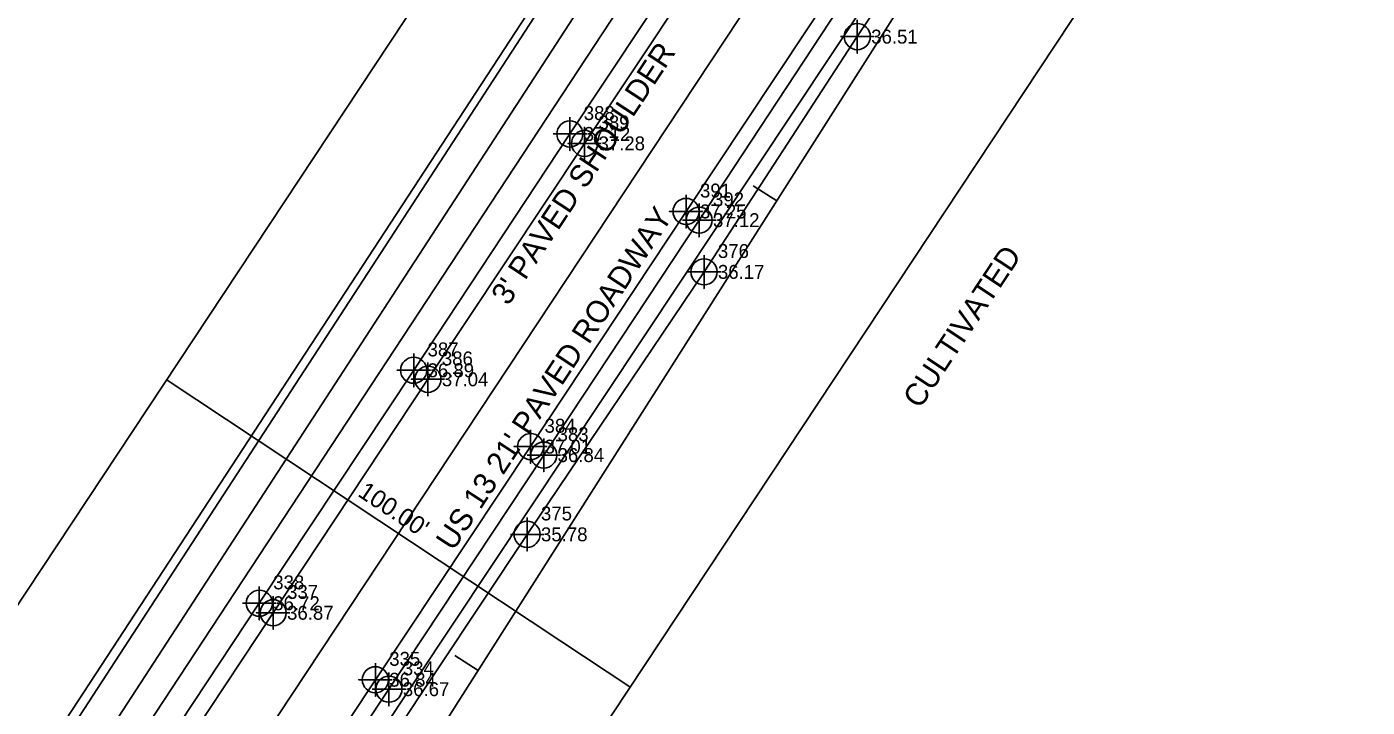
# Model space of a CAD drawing. Extents: x 2603627 to 2605187, y 896619 to 899063.
# Drawn here: x 2604841.7 to 2605082.8, y 898680.4 to 898802.7 of the extents above; entities that cross this region are included whole.
import ezdxf

# ---------------------------------------------------------------- set-up
doc = ezdxf.new("R2010")
doc.units = 0
for name, color, linetype in [('Exist Horizontal Alignment', 7, 'Continuous'), ('Exist Horizontal Baseline Alignment', 7, 'Continuous'), ('Exist Horizontal Baseline Alignment Tick small', 7, 'Continuous'), ('Exist Other Culture Area Outline Text', 7, 'Continuous'), ('Exist Right of Way Line', 7, 'Continuous'), ('Exist Right of Way Width CELL', 7, 'Continuous'), ('Exist Roads EOP', 7, 'Continuous'), ('Exist Roads EOP Cogo Elevation', 7, 'Continuous'), ('Exist Roads EOP Cogo Number', 7, 'Continuous'), ('Exist Roads EOP Cogo Point CELL', 7, 'Continuous'), ('Exist Roads EOP Text', 7, 'Continuous'), ('Exist Roads EOT', 7, 'Continuous'), ('Exist Roads EOT Cogo Elevation', 7, 'Continuous'), ('Exist Roads EOT Cogo Number', 7, 'Continuous'), ('Exist Roads EOT Cogo Point CELL', 7, 'Continuous'), ('Exist Roads EOT Text', 7, 'Continuous'), ('Exist Utilities Telephone UG Cable SUE LOS C', 7, 'Continuous'), ('Exist Utilities Telephone UG FO SUE LOS C', 7, 'Continuous'), ('Exist Utilities Water UG Line SUE LOS B', 7, 'Continuous'), ('Exist Utilities Water UG Line SUE LOS B Cogo Elevation', 7, 'Continuous'), ('Exist Utilities Water UG Line SUE LOS B Cogo Number', 7, 'Continuous'), ('Exist Utilities Water UG Line SUE LOS B Cogo Point CELL', 7, 'Continuous')]:
    doc.layers.add(name, color=color, linetype=linetype)

# ---------------------------------------------------------------- blocks, each defined once
blk = doc.blocks.new('EXIST ROADS EOP COGO POINT')
at = {"layer": 'Exist Roads EOP Cogo Point CELL'}
blk.add_lwpolyline([(0, 0.06), (0, -0.06), (0, 0), (0.06, 0), (-0.06, 0)], dxfattribs=at)
blk.add_circle((0, 0), 0.0469, dxfattribs=at)
blk = doc.blocks.new('EXIST ROADS EOT COGO POINT')
at = {"layer": 'Exist Roads EOT Cogo Point CELL'}
blk.add_lwpolyline([(0, 0.06), (0, -0.06), (0, 0), (-0.06, 0), (0.06, 0)], dxfattribs=at)
blk.add_circle((0, 0), 0.0469, dxfattribs=at)
blk = doc.blocks.new('EXIST UTILITIES WATER UG LINE SUE LOS B COGO POINT')
at = {"layer": 'Exist Utilities Water UG Line SUE LOS B Cogo Point CELL'}
blk.add_lwpolyline([(0, 0.06), (0, -0.06), (0, 0), (0.06, 0), (-0.06, 0)], dxfattribs=at)
blk.add_circle((0, 0), 0.0469, dxfattribs=at)

msp = doc.modelspace()

# ---------------------------------------------------------------- linework, layer by layer
at = {"layer": 'Exist Horizontal Alignment'}
msp.add_line((2604681.44, 898368.79), (2605041.11, 898911.74), dxfattribs=at)
at = {"layer": 'Exist Horizontal Baseline Alignment'}
msp.add_line((2604793.6, 898483.9), (2605028.26, 898852.56), dxfattribs=at)
at = {"layer": 'Exist Horizontal Baseline Alignment Tick small'}
for p, q in [((2604976.59, 898771.39), (2604972.37, 898774.07)), ((2604922.89, 898687.03), (2604918.68, 898689.71))]:
    msp.add_line(p, q, dxfattribs=at)
at = {"layer": 'Exist Right of Way Line'}
for p, q in [((2604639.76, 898396.41), (2604999.42, 898939.36)), ((2604723.13, 898341.18), (2605082.79, 898884.13))]:
    msp.add_line(p, q, dxfattribs=at)
at = {"layer": 'Exist Right of Way Width CELL'}
for p in [(2604866.8, 898739.31), (2604950.17, 898684.08)]:
    msp.add_line(p, (2604937.78, 898692.29), dxfattribs=at)
at = {"layer": 'Exist Roads EOP'}
for points in [[(2604577.96, 898237.27), (2604606.45, 898281.24), (2604633.89, 898322.5), (2604662.45, 898365.47), (2604690.62, 898408.06), (2604717.29, 898448.09), (2604745.46, 898490.11), (2604773.6, 898532.6), (2604800.88, 898573.95), (2604828.34, 898615.46), (2604855.1, 898656.15), (2604883.53, 898699.09), (2604911.29, 898740.95), (2604939.38, 898783.41), (2604966.33, 898824.04), (2604993.38, 898865.27), (2605022.2, 898908.38), (2605029.46, 898919.46)], [(2604713.86, 898392.44), (2604740.28, 898432.25), (2604768.45, 898474.26), (2604797.27, 898517.92), (2604823.93, 898558.47), (2604851.31, 898599.84), (2604878.52, 898641.09), (2604906.84, 898683.65), (2604934.68, 898725.71), (2604962.63, 898767.92), (2604989.32, 898808.49), (2605016.42, 898849.59), (2605045.34, 898893.33), (2605052.55, 898904.16)]]:
    msp.add_lwpolyline(points, dxfattribs=at)
at = {"layer": 'Exist Roads EOT'}
for points in [[(2604580.65, 898235.67), (2604609.23, 898279.3), (2604636.66, 898320.72), (2604665.18, 898363.91), (2604693.37, 898406.36), (2604719.95, 898446.05), (2604748, 898488.34), (2604776.15, 898530.84), (2604803.5, 898572.3), (2604830.95, 898613.91), (2604857.58, 898654.47), (2604886.02, 898697.38), (2604913.86, 898739.33), (2604942.03, 898781.72), (2604969.06, 898822.38), (2604996.07, 898863.44), (2605024.73, 898906.73), (2605032, 898917.78)], [(2604598.04, 898223.4), (2604627.23, 898267.23), (2604654.64, 898308.57), (2604683.28, 898352.01), (2604711.27, 898394.14), (2604737.98, 898434.05), (2604766.04, 898475.94), (2604794.96, 898519.26), (2604821.61, 898559.82), (2604848.89, 898601.4), (2604876.12, 898642.73), (2604904.4, 898685.35), (2604932.33, 898727.23), (2604960.29, 898769.49), (2604987.32, 898810.19), (2605014.12, 898850.95), (2605043.08, 898894.89), (2605050.2, 898905.72)]]:
    msp.add_lwpolyline(points, dxfattribs=at)
at = {"layer": 'Exist Utilities Telephone UG Cable SUE LOS C'}
for p, q in [((2604852.96, 898684.66), (2605013.55, 898930.01)), ((2604797.03, 898576.37), (2605024.91, 898922.48)), ((2604850.74, 898593.69), (2605031.63, 898865.69)), ((2604658.71, 898389.49), (2604852.96, 898684.66))]:
    msp.add_line(p, q, dxfattribs=at)
at = {"layer": 'Exist Utilities Telephone UG FO SUE LOS C'}
for p, q in [((2604671.2, 898402.26), (2605014.35, 898929.48)), ((2604676.14, 898398.98), (2605019.3, 898926.2))]:
    msp.add_line(p, q, dxfattribs=at)
at = {"layer": 'Exist Utilities Water UG Line SUE LOS B'}
msp.add_lwpolyline([(2604590.41, 898183.07), (2604608.13, 898210.78), (2604631.33, 898247.72), (2604631.98, 898248.77), (2604637.93, 898260.9), (2604650.01, 898281.75), (2604670.13, 898312.66), (2604706.14, 898370.49), (2604744.2, 898428.79), (2604775.85, 898478.14), (2604817.62, 898541.22), (2604844.76, 898580.18), (2604876.2, 898627.22), (2604907.55, 898675.15), (2604931.69, 898711.47), (2604963.51, 898758.63), (2604991.08, 898800.9), (2605022.23, 898847.26), (2605044.13, 898880.13), (2605057.71, 898900.74)], dxfattribs=at)

# ---------------------------------------------------------------- block references
at = {"layer": 'Exist Roads EOP Cogo Point CELL', "xscale": 50, "yscale": 50}
for p in [(2604939.38, 898783.41), (2604962.63, 898767.92), (2604911.29, 898740.95), (2604934.68, 898725.71), (2604883.53, 898699.09), (2604906.84, 898683.65)]:
    msp.add_blockref('EXIST ROADS EOP COGO POINT', p, dxfattribs=at)
at = {"layer": 'Exist Roads EOT Cogo Point CELL', "xscale": 50, "yscale": 50}
for p in [(2604942.03, 898781.72), (2604960.29, 898769.49), (2604913.86, 898739.33), (2604932.33, 898727.23), (2604886.02, 898697.38), (2604904.4, 898685.35)]:
    msp.add_blockref('EXIST ROADS EOT COGO POINT', p, dxfattribs=at)
at = {"layer": 'Exist Utilities Water UG Line SUE LOS B Cogo Point CELL', "xscale": 50, "yscale": 50}
for p in [(2604991.08, 898800.9), (2604963.51, 898758.63), (2604931.69, 898711.47)]:
    msp.add_blockref('EXIST UTILITIES WATER UG LINE SUE LOS B COGO POINT', p, dxfattribs=at)

# ---------------------------------------------------------------- texts
at = {"layer": 'Exist Other Culture Area Outline Text'}
msp.add_text('CULTIVATED', height=4, rotation=56.4786, dxfattribs=at).set_placement((2605002.37, 898733.86))
at = {"layer": 'Exist Right of Way Width CELL'}
msp.add_text("100.00'", height=3.2, rotation=326.4785, dxfattribs=at).set_placement((2604901.06, 898718.46))
at = {"layer": 'Exist Roads EOP Cogo Elevation'}
for s, p in [('37.12', (2604941.88, 898782.16)), ('37.12', (2604965.13, 898766.67)), ('36.89', (2604913.79, 898739.7)), ('36.84', (2604937.18, 898724.46)), ('36.72', (2604886.03, 898697.84)), ('36.67', (2604909.34, 898682.4))]:
    msp.add_text(s, height=2.5, dxfattribs=at).set_placement(p)
at = {"layer": 'Exist Roads EOP Cogo Number'}
for s, p in [('388', (2604941.88, 898785.91)), ('392', (2604965.13, 898770.42)), ('387', (2604913.79, 898743.45)), ('383', (2604937.18, 898728.21)), ('338', (2604886.03, 898701.59)), ('334', (2604909.34, 898686.15))]:
    msp.add_text(s, height=2.5, dxfattribs=at).set_placement(p)
at = {"layer": 'Exist Roads EOP Text'}
msp.add_text("3' PAVED SHOULDER", height=4, rotation=56.5107, dxfattribs=at).set_placement((2604928.31, 898752.4))
at = {"layer": 'Exist Roads EOT Cogo Elevation'}
for s, p in [('37.28', (2604944.53, 898780.47)), ('37.25', (2604962.79, 898768.24)), ('37.04', (2604916.36, 898738.08)), ('37.01', (2604934.83, 898725.98)), ('36.87', (2604888.52, 898696.13)), ('36.84', (2604906.9, 898684.1))]:
    msp.add_text(s, height=2.5, dxfattribs=at).set_placement(p)
at = {"layer": 'Exist Roads EOT Cogo Number'}
for s, p in [('389', (2604944.53, 898784.22)), ('391', (2604962.79, 898771.99)), ('386', (2604916.36, 898741.83)), ('384', (2604934.83, 898729.73)), ('337', (2604888.52, 898699.88)), ('335', (2604906.9, 898687.85))]:
    msp.add_text(s, height=2.5, dxfattribs=at).set_placement(p)
at = {"layer": 'Exist Roads EOT Text'}
msp.add_text(" US 13 21' PAVED ROADWAY", height=4, rotation=56.6698, dxfattribs=at).set_placement((2604917.57, 898707.07))
at = {"layer": 'Exist Utilities Water UG Line SUE LOS B Cogo Elevation'}
for s, p in [('36.51', (2604993.58, 898799.65)), ('36.17', (2604966.01, 898757.38)), ('35.78', (2604934.19, 898710.22))]:
    msp.add_text(s, height=2.5, dxfattribs=at).set_placement(p)
at = {"layer": 'Exist Utilities Water UG Line SUE LOS B Cogo Number'}
for s, p in [('376', (2604966.01, 898761.13)), ('375', (2604934.19, 898713.97))]:
    msp.add_text(s, height=2.5, dxfattribs=at).set_placement(p)

doc.saveas('drawing.dxf')
